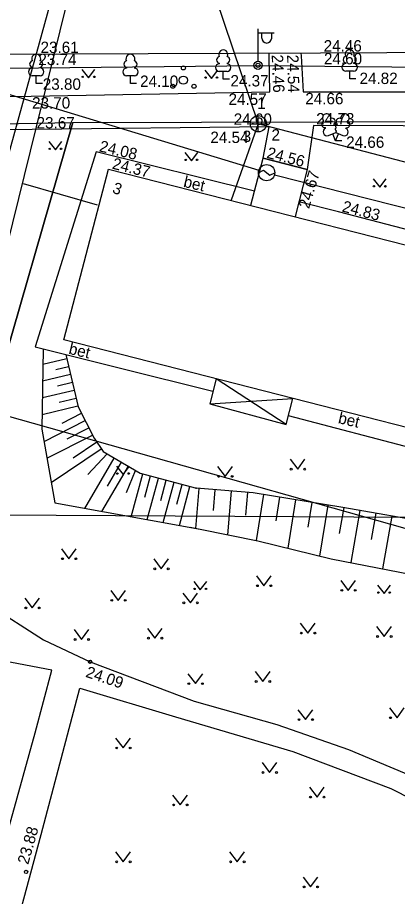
# Model space of a CAD drawing. Extents: x 714391 to 714584, y 6589993 to 6590151.
# Drawn here: x 714529 to 714552.3, y 6590039.4 to 6590093.4 of the extents above; entities that cross this region are included whole.
import ezdxf

# ---------------------------------------------------------------- set-up
doc = ezdxf.new("R2010")
doc.units = 0
for name, color, linetype in [('HALJASTUS', 7, 'Continuous'), ('HOONE', 7, 'Continuous'), ('HOONEDET', 7, 'Continuous'), ('KKAEV', 7, 'Continuous'), ('KORGUS', 7, 'Continuous'), ('KTRASS', 7, 'Continuous'), ('MPKAABEL', 7, 'Continuous'), ('POST', 7, 'Continuous'), ('PUU', 7, 'Continuous'), ('RELJEEF', 7, 'Continuous'), ('SKTRASS', 7, 'Continuous'), ('TEE', 7, 'Continuous'), ('TORU NR', 7, 'Continuous'), ('TTRASS', 7, 'Continuous'), ('Слой 1', 7, 'Continuous')]:
    doc.layers.add(name, color=color, linetype=linetype)

msp = doc.modelspace()

# ---------------------------------------------------------------- linework, layer by layer
at = {"layer": 'HALJASTUS'}
for p, q in [((714532.967, 6590090.202), (714533.372, 6590089.697)), ((714533.372, 6590089.697), (714533.767, 6590090.202)), ((714540.508, 6590090.157), (714540.913, 6590089.652)), ((714540.913, 6590089.652), (714541.308, 6590090.157)), ((714530.935, 6590085.777), (714531.34, 6590085.272)), ((714531.34, 6590085.272), (714531.735, 6590085.777)), ((714539.289, 6590085.1), (714539.694, 6590084.595)), ((714539.694, 6590084.595), (714540.089, 6590085.1)), ((714550.848, 6590083.474), (714551.253, 6590082.969)), ((714551.253, 6590082.969), (714551.648, 6590083.474)), ((714535.09, 6590065.819), (714535.495, 6590065.314)), ((714535.495, 6590065.314), (714535.89, 6590065.819)), ((714541.301, 6590065.801), (714541.764, 6590065.194)), ((714541.764, 6590065.194), (714542.21, 6590065.801)), ((714545.755, 6590066.246), (714546.218, 6590065.639)), ((714546.218, 6590065.639), (714546.664, 6590066.246)), ((714531.707, 6590060.741), (714532.17, 6590060.134)), ((714532.17, 6590060.134), (714532.616, 6590060.741)), ((714537.375, 6590060.121), (714537.838, 6590059.514)), ((714537.838, 6590059.514), (714538.284, 6590060.121)), ((714543.678, 6590059.08), (714544.141, 6590058.473)), ((714544.141, 6590058.473), (714544.587, 6590059.08)), ((714548.862, 6590058.796), (714549.325, 6590058.189)), ((714549.325, 6590058.189), (714549.771, 6590058.796)), ((714539.831, 6590058.73), (714540.236, 6590058.225)), ((714540.236, 6590058.225), (714540.631, 6590058.73)), ((714551.119, 6590058.504), (714551.524, 6590057.999)), ((714551.524, 6590057.999), (714551.919, 6590058.504)), ((714529.455, 6590057.716), (714529.918, 6590057.109)), ((714529.918, 6590057.109), (714530.364, 6590057.716)), ((714534.735, 6590058.181), (714535.198, 6590057.574)), ((714535.198, 6590057.574), (714535.644, 6590058.181)), ((714539.161, 6590058.026), (714539.624, 6590057.419)), ((714539.624, 6590057.419), (714540.07, 6590058.026)), ((714546.376, 6590056.171), (714546.839, 6590055.564)), ((714546.839, 6590055.564), (714547.285, 6590056.171)), ((714532.483, 6590055.776), (714532.946, 6590055.169)), ((714532.946, 6590055.169), (714533.392, 6590055.776)), ((714536.987, 6590055.854), (714537.45, 6590055.247)), ((714537.45, 6590055.247), (714537.896, 6590055.854)), ((714551.063, 6590055.958), (714551.526, 6590055.351)), ((714551.526, 6590055.351), (714551.972, 6590055.958)), ((714539.472, 6590053.061), (714539.935, 6590052.454)), ((714539.935, 6590052.454), (714540.381, 6590053.061)), ((714543.607, 6590053.191), (714544.07, 6590052.584)), ((714544.07, 6590052.584), (714544.516, 6590053.191)), ((714546.234, 6590050.85), (714546.697, 6590050.243)), ((714546.697, 6590050.243), (714547.143, 6590050.85)), ((714551.855, 6590050.966), (714552.318, 6590050.359)), ((714552.318, 6590050.359), (714552.764, 6590050.966)), ((714535.037, 6590049.107), (714535.5, 6590048.5)), ((714535.5, 6590048.5), (714535.946, 6590049.107)), ((714544.025, 6590047.601), (714544.488, 6590046.994)), ((714544.488, 6590046.994), (714544.934, 6590047.601)), ((714546.94, 6590046.089), (714547.403, 6590045.482)), ((714547.403, 6590045.482), (714547.849, 6590046.089)), ((714538.537, 6590045.607), (714539, 6590045)), ((714539, 6590045), (714539.446, 6590045.607)), ((714535.037, 6590042.107), (714535.5, 6590041.5)), ((714535.5, 6590041.5), (714535.946, 6590042.107)), ((714542.037, 6590042.107), (714542.5, 6590041.5)), ((714542.5, 6590041.5), (714542.946, 6590042.107)), ((714546.549, 6590040.566), (714547.012, 6590039.959)), ((714547.012, 6590039.959), (714547.458, 6590040.566))]:
    msp.add_line(p, q, dxfattribs=at)
for centre, radius in [((714539.197, 6590090.299), 0.125), ((714533.019, 6590089.752), 0.0428), ((714533.719, 6590089.752), 0.0452), ((714539.197, 6590089.549), 0.25), ((714540.56, 6590089.707), 0.0428), ((714541.26, 6590089.707), 0.0452), ((714538.547, 6590089.174), 0.125), ((714539.847, 6590089.174), 0.125), ((714530.987, 6590085.327), 0.0428), ((714531.687, 6590085.327), 0.0452), ((714539.341, 6590084.65), 0.0428), ((714540.041, 6590084.65), 0.0452), ((714550.9, 6590083.024), 0.0428), ((714551.6, 6590083.024), 0.0452), ((714535.142, 6590065.37), 0.0428), ((714535.842, 6590065.37), 0.0452), ((714541.363, 6590065.194), 0.055), ((714542.192, 6590065.194), 0.055), ((714545.817, 6590065.639), 0.055), ((714546.646, 6590065.639), 0.055), ((714531.769, 6590060.134), 0.055), ((714532.598, 6590060.134), 0.055), ((714537.437, 6590059.514), 0.055), ((714538.266, 6590059.514), 0.055), ((714539.883, 6590058.28), 0.0428), ((714540.583, 6590058.28), 0.0452), ((714543.74, 6590058.473), 0.055), ((714544.569, 6590058.473), 0.055), ((714548.924, 6590058.189), 0.055), ((714549.753, 6590058.189), 0.055), ((714551.171, 6590058.055), 0.0428), ((714551.871, 6590058.055), 0.0452), ((714529.517, 6590057.109), 0.055), ((714530.346, 6590057.109), 0.055), ((714534.797, 6590057.574), 0.055), ((714535.626, 6590057.574), 0.055), ((714539.223, 6590057.419), 0.055), ((714540.052, 6590057.419), 0.055), ((714546.438, 6590055.564), 0.055), ((714547.267, 6590055.564), 0.055), ((714532.545, 6590055.169), 0.055), ((714533.374, 6590055.169), 0.055), ((714537.049, 6590055.247), 0.055), ((714537.878, 6590055.247), 0.055), ((714551.125, 6590055.351), 0.055), ((714551.954, 6590055.351), 0.055), ((714539.534, 6590052.454), 0.055), ((714540.363, 6590052.454), 0.055), ((714543.669, 6590052.584), 0.055), ((714544.498, 6590052.584), 0.055), ((714546.296, 6590050.243), 0.055), ((714547.125, 6590050.243), 0.055), ((714551.917, 6590050.359), 0.055), ((714535.099, 6590048.5), 0.055), ((714535.928, 6590048.5), 0.055), ((714544.087, 6590046.994), 0.055), ((714544.916, 6590046.994), 0.055), ((714547.002, 6590045.482), 0.055), ((714547.831, 6590045.482), 0.055), ((714538.599, 6590045), 0.055), ((714539.428, 6590045), 0.055), ((714535.099, 6590041.5), 0.055), ((714535.928, 6590041.5), 0.055), ((714542.099, 6590041.5), 0.055), ((714542.928, 6590041.5), 0.055), ((714546.611, 6590039.959), 0.055), ((714547.44, 6590039.959), 0.055)]:
    msp.add_circle(centre, radius, dxfattribs=at)
at = {"layer": 'HOONE'}
for p, q in [((714543.807, 6590083.861), (714544.107, 6590084.011)), ((714544.107, 6590084.011), (714544.507, 6590083.711)), ((714544.507, 6590083.711), (714544.807, 6590083.861)), ((714544.792, 6590083.737), (714563.294, 6590079.021))]:
    msp.add_line(p, q, dxfattribs=at)
for points in [[(714462.976, 6590094.666), (714464.039, 6590094.043), (714487.101, 6590093.963), (714494.525, 6590093.286), (714520.217, 6590091.196), (714543.829, 6590084.007)], [(714543.336, 6590081.86), (714544.103, 6590084.747), (714546.8, 6590084.063), (714546.052, 6590081.166)], [(714571.553, 6590063.416), (714531.849, 6590073.579), (714534.607, 6590084.082)], [(714534.607, 6590084.082), (714574.255, 6590073.951), (714571.553, 6590063.416)], [(714541.207, 6590071.184), (714540.811, 6590069.652), (714545.499, 6590068.383), (714545.912, 6590069.979)]]:
    msp.add_lwpolyline(points, dxfattribs=at)
msp.add_circle((714544.307, 6590083.861), 0.5, dxfattribs=at)
at = {"layer": 'HOONEDET'}
for p, q in [((714546.8, 6590084.063), (714544.103, 6590084.747)), ((714545.499, 6590068.383), (714541.207, 6590071.184)), ((714540.811, 6590069.652), (714545.912, 6590069.979))]:
    msp.add_line(p, q, dxfattribs=at)
at = {"layer": 'KKAEV'}
for p, q in [((714543.798, 6590086.368), (714543.798, 6590087.368)), ((714543.298, 6590086.868), (714544.298, 6590086.868))]:
    msp.add_line(p, q, dxfattribs=at)
msp.add_circle((714543.798, 6590086.868), 0.5, dxfattribs=at)
at = {"layer": 'KORGUS'}
for centre in [(714533.466, 6590053.803), (714529.534, 6590040.884)]:
    msp.add_circle(centre, 0.1, dxfattribs=at)
at = {"layer": 'KTRASS'}
for p, q in [((714540.165, 6590097.573), (714543.798, 6590086.868)), ((714543.798, 6590086.868), (714542.121, 6590082.162)), ((714563.101, 6590081.794), (714543.798, 6590086.868))]:
    msp.add_line(p, q, dxfattribs=at)
at = {"layer": 'MPKAABEL'}
for points in [[(714460.809, 6590089.818), (714516.791, 6590090.163), (714543.78, 6590090.458), (714574.561, 6590090.139)], [(714558.719, 6590063.793), (714557.614, 6590062.993), (714553.32, 6590062.662), (714527.694, 6590062.802), (714519.691, 6590062.433), (714508.979, 6590063.853), (714473.93, 6590041.599)]]:
    msp.add_lwpolyline(points, dxfattribs=at)
at = {"layer": 'POST'}
for p, q in [((714543.78, 6590090.708), (714543.78, 6590092.708)), ((714543.78, 6590092.458), (714544.78, 6590092.458)), ((714544.007, 6590092.137), (714544.007, 6590092.458)), ((714544.619, 6590092.137), (714544.619, 6590092.458)), ((714543.78, 6590090.458), (714543.78, 6590090.458))]:
    msp.add_line(p, q, dxfattribs=at)
for radius in [0.25, 0.127]:
    msp.add_circle((714543.78, 6590090.458), radius, dxfattribs=at)
msp.add_arc((714544.313, 6590092.137), 0.306, 180, 0, dxfattribs=at)
at = {"layer": 'PUU'}
for p, q in [((714529.917, 6590090.328), (714529.917, 6590090.298)), ((714530.397, 6590090.328), (714530.397, 6590090.298)), ((714535.706, 6590090.324), (714535.706, 6590090.294)), ((714536.186, 6590090.324), (714536.186, 6590090.294)), ((714541.402, 6590090.587), (714541.402, 6590090.557)), ((714541.882, 6590090.082), (714541.402, 6590090.082)), ((714541.642, 6590089.607), (714541.642, 6590090.082)), ((714541.882, 6590090.587), (714541.882, 6590090.557)), ((714549.172, 6590090.602), (714549.172, 6590090.572)), ((714549.652, 6590090.097), (714549.172, 6590090.097)), ((714549.412, 6590089.622), (714549.412, 6590090.097)), ((714549.652, 6590090.602), (714549.652, 6590090.572)), ((714530.397, 6590089.823), (714529.917, 6590089.823)), ((714530.157, 6590089.348), (714530.157, 6590089.823)), ((714536.186, 6590089.819), (714535.706, 6590089.819)), ((714535.946, 6590089.344), (714535.946, 6590089.819)), ((714542.022, 6590089.607), (714541.642, 6590089.607)), ((714549.792, 6590089.622), (714549.412, 6590089.622)), ((714530.537, 6590089.348), (714530.157, 6590089.348)), ((714536.326, 6590089.344), (714535.946, 6590089.344)), ((714548.459, 6590086.803), (714548.444, 6590086.838)), ((714548.644, 6590086.798), (714548.659, 6590086.838)), ((714547.929, 6590086.593), (714547.914, 6590086.633)), ((714548.104, 6590086.148), (714548.549, 6590086.323)), ((714548.549, 6590086.323), (714548.989, 6590086.143)), ((714549.169, 6590086.583), (714549.184, 6590086.623)), ((714548.544, 6590085.813), (714548.369, 6590086.253)), ((714548.544, 6590085.813), (714548.724, 6590086.253)), ((714548.924, 6590085.813), (714548.544, 6590085.813))]:
    msp.add_line(p, q, dxfattribs=at)
msp.add_lwpolyline([(714548.549, 6590086.818), (714548.529, 6590086.743), (714548.529, 6590086.723), (714548.539, 6590086.693), (714548.559, 6590086.658), (714548.564, 6590086.638), (714548.549, 6590086.603), (714548.524, 6590086.553), (714548.519, 6590086.528), (714548.524, 6590086.513), (714548.534, 6590086.483), (714548.569, 6590086.423), (714548.574, 6590086.403), (714548.569, 6590086.383), (714548.554, 6590086.348), (714548.549, 6590086.323)], dxfattribs=at)
for centre, radius, start, end in [((714541.642, 6590091.127), 0.277, 332.5799, 207.4201), ((714549.412, 6590091.142), 0.277, 332.5799, 207.4201), ((714529.967, 6590090.536), 0.212, 105.2441, 257.079), ((714530.157, 6590090.868), 0.277, 332.5799, 207.4201), ((714530.347, 6590090.536), 0.212, 282.921, 74.7559), ((714535.756, 6590090.531), 0.212, 105.2441, 257.079), ((714535.946, 6590090.864), 0.277, 332.5799, 207.4201), ((714536.136, 6590090.531), 0.212, 282.921, 74.7559), ((714541.452, 6590090.795), 0.212, 105.2441, 257.079), ((714541.832, 6590090.795), 0.212, 282.921, 74.7559), ((714549.222, 6590090.81), 0.212, 105.2441, 257.079), ((714549.602, 6590090.81), 0.212, 282.921, 74.7559), ((714529.919, 6590090.061), 0.237, 90, 270), ((714530.394, 6590090.061), 0.237, 270, 90), ((714535.708, 6590090.056), 0.237, 90, 270), ((714536.183, 6590090.056), 0.237, 270, 90), ((714541.404, 6590090.32), 0.237, 90, 270), ((714541.879, 6590090.32), 0.237, 270, 90), ((714549.174, 6590090.335), 0.237, 90, 270), ((714549.649, 6590090.335), 0.237, 270, 90), ((714547.987, 6590087.227), 0.256, 111.5027, 232.5173), ((714547.987, 6590087.227), 0.256, 350.4856, 111.5002), ((714549.123, 6590087.218), 0.256, 67.6168, 188.6314), ((714549.123, 6590087.218), 0.256, 306.5997, 67.6143), ((714547.888, 6590086.831), 0.202, 106.2979, 277.8684), ((714548.33, 6590087.005), 0.202, 305.1345, 116.705), ((714548.777, 6590087.001), 0.202, 62.412, 233.9825), ((714549.216, 6590086.821), 0.202, 261.2486, 72.8191), ((714548.018, 6590086.371), 0.237, 111.5014, 291.5004), ((714548.548, 6590086.58), 0.237, 66.7655, 111.5015), ((714549.079, 6590086.363), 0.237, 247.6166, 67.6155)]:
    msp.add_arc(centre, radius, start, end, dxfattribs=at)
at = {"layer": 'RELJEEF'}
for p, q in [((714530.569, 6590072.097), (714532.033, 6590072.442)), ((714531.354, 6590071.768), (714532.148, 6590071.955)), ((714530.552, 6590071.066), (714532.262, 6590071.468)), ((714531.46, 6590070.766), (714532.377, 6590070.982)), ((714530.535, 6590070.035), (714532.491, 6590070.495)), ((714531.566, 6590069.764), (714532.606, 6590070.008)), ((714530.519, 6590069.003), (714532.72, 6590069.521)), ((714531.742, 6590068.461), (714532.936, 6590069.072)), ((714530.637, 6590067.335), (714533.164, 6590068.627)), ((714532.06, 6590067.501), (714533.392, 6590068.182)), ((714530.818, 6590066.305), (714533.619, 6590067.736)), ((714531.08, 6590064.809), (714534.157, 6590066.895)), ((714532.431, 6590066.329), (714533.876, 6590067.309)), ((714533.15, 6590063.228), (714534.955, 6590066.32)), ((714533.324, 6590065.306), (714534.523, 6590066.572)), ((714534.198, 6590063.039), (714535.819, 6590065.816)), ((714534.53, 6590064.601), (714535.387, 6590066.068)), ((714535.695, 6590064.211), (714536.25, 6590065.564)), ((714535.987, 6590062.717), (714536.699, 6590065.353)), ((714536.832, 6590063.925), (714537.182, 6590065.223)), ((714536.975, 6590062.539), (714537.665, 6590065.092)), ((714537.808, 6590063.706), (714538.147, 6590064.962)), ((714537.963, 6590062.361), (714538.63, 6590064.832)), ((714538.785, 6590063.486), (714539.113, 6590064.701)), ((714538.951, 6590062.182), (714539.596, 6590064.571))]:
    msp.add_line(p, q, dxfattribs=at)
for points in [[(714530.584, 6590073.038), (714530.504, 6590068.094), (714531.299, 6590063.562), (714540.223, 6590061.953)], [(714531.976, 6590072.685), (714532.732, 6590069.472), (714533.719, 6590067.541), (714534.279, 6590066.715), (714536.537, 6590065.397), (714539.992, 6590064.464)], [(714539.957, 6590062), (714540.158, 6590064.451)], [(714539.958, 6590064.473), (714539.992, 6590064.464)], [(714565.692, 6590059.595), (714563.686, 6590060.51), (714558.32, 6590061.614), (714554.618, 6590062.293), (714548.983, 6590063.29), (714543.482, 6590064.178), (714539.992, 6590064.464), (714539.958, 6590064.473)], [(714541.049, 6590063.087), (714541.154, 6590064.369)], [(714541.931, 6590061.605), (714542.151, 6590064.288)], [(714543.033, 6590062.805), (714543.148, 6590064.206)], [(714543.682, 6590061.248), (714544.138, 6590064.072)], [(714544.891, 6590062.463), (714545.125, 6590063.913)], [(714545.631, 6590060.776), (714546.112, 6590063.753)], [(714546.853, 6590062.066), (714547.1, 6590063.594)], [(714547.58, 6590060.3), (714548.087, 6590063.434)], [(714548.792, 6590061.679), (714549.074, 6590063.273)], [(714549.492, 6590059.894), (714550.058, 6590063.099)], [(714550.758, 6590061.314), (714551.043, 6590062.925)], [(714551.455, 6590059.513), (714552.028, 6590062.751)], [(714539.606, 6590062.064), (714540.223, 6590061.953)], [(714539.606, 6590062.064), (714540.223, 6590061.953), (714543.767, 6590061.231), (714548.275, 6590060.13), (714553.23, 6590059.168), (714558.369, 6590057.882), (714560.606, 6590056.851), (714561.638, 6590054.857), (714561.432, 6590053.929), (714559.208, 6590049.705), (714554.662, 6590046.175)]]:
    msp.add_lwpolyline(points, dxfattribs=at)
at = {"layer": 'SKTRASS'}
msp.add_lwpolyline([(714531.495, 6590096.001), (714522.972, 6590065.168), (714519.718, 6590053.426), (714509.807, 6590017.772), (714505.951, 6590002.864)], dxfattribs=at)
at = {"layer": 'TEE'}
msp.add_line((714545.64, 6590068.929), (714557.142, 6590065.913), dxfattribs=at)
for points in [[(714573.651, 6590091.235), (714563.941, 6590091.279), (714547.616, 6590091.212), (714515.821, 6590091.083), (714495.803, 6590091.003), (714475.803, 6590090.885), (714460.229, 6590090.83)], [(714515.67, 6590091.082), (714515.674, 6590090.929), (714515.742, 6590088.532), (714529.854, 6590088.565), (714544.514, 6590088.837), (714544.463, 6590091.007), (714544.458, 6590091.199)], [(714546.418, 6590091.207), (714546.428, 6590091.036), (714546.556, 6590088.84)], [(714546.556, 6590088.84), (714546.656, 6590088.84), (714563.739, 6590088.838), (714563.771, 6590091.085), (714563.774, 6590091.278)], [(714544.103, 6590084.747), (714544.474, 6590086.687), (714529.917, 6590086.508), (714515.394, 6590086.496), (714515.277, 6590077.587)], [(714563.164, 6590078.293), (714563.571, 6590080.29), (714563.722, 6590086.695), (714547.192, 6590086.755), (714546.8, 6590084.063)], [(714533.834, 6590085.137), (714530.086, 6590073.165), (714535.337, 6590071.847), (714541.01, 6590070.424)], [(714543.568, 6590082.732), (714533.834, 6590085.137)], [(714563.025, 6590077.723), (714548.722, 6590081.458), (714546.283, 6590082.061)], [(714523.83, 6590060.323), (714524.838, 6590059.346), (714527.207, 6590057.322), (714530.612, 6590055.143), (714533.466, 6590053.803), (714539.862, 6590051.373), (714544.939, 6590049.949), (714549.327, 6590048.405), (714554.662, 6590046.175), (714555.973, 6590045.43), (714557.565, 6590044.068), (714560.558, 6590042.157), (714562.991, 6590040.414), (714566.112, 6590037.695), (714570.003, 6590051.519), (714571.762, 6590062.449)], [(714525.477, 6590005.373), (714525.684, 6590006.074), (714527.69, 6590005.573), (714531.538, 6590012.432), (714532.385, 6590015.369), (714531.445, 6590019.084), (714529.795, 6590023.709), (714527.067, 6590029.841), (714526.32, 6590032.242), (714526.158, 6590034.948), (714527.384, 6590039.748), (714530.089, 6590049.424), (714531.112, 6590053.289), (714520.888, 6590055.232), (714516.962, 6590040.074), (714512.15, 6590039.854), (714507.831, 6590037.94), (714505.233, 6590035.896), (714491.681, 6590027.029), (714484.169, 6590021.661), (714470.258, 6590012.413)], [(714530.594, 6590004.671), (714529.575, 6590005.355), (714533.957, 6590012.977), (714534.157, 6590015.322), (714534.216, 6590016.497), (714533.749, 6590019.201), (714531.843, 6590023.902), (714529.246, 6590029.211), (714527.989, 6590032.696), (714528.19, 6590034.745), (714530.462, 6590043.175), (714532.838, 6590052.177), (714538.719, 6590050.416), (714545.918, 6590048.286), (714551.944, 6590046.002), (714557.184, 6590043.351), (714560.131, 6590041.46), (714562.296, 6590039.644), (714565.486, 6590037.034), (714564.832, 6590036.22), (714560.292, 6590037.889), (714555.09, 6590040.381)]]:
    msp.add_lwpolyline(points, dxfattribs=at)
at = {"layer": 'TTRASS'}
msp.add_line((714529.363, 6590083.201), (714533.906, 6590081.883), dxfattribs=at)
msp.add_lwpolyline([(714510.928, 6590008.703), (714512.829, 6590017.079), (714522.511, 6590055.684), (714522.522, 6590055.681), (714534.537, 6590104.393)], dxfattribs=at)
at = {"layer": 'Слой 1'}
for points in [[(714478.99, 6590085.97), (714532.4, 6590086.95), (714527.28, 6590069.21), (714523.84, 6590056.54), (714478.28, 6590068.22)], [(714579.84, 6590087.07), (714574.08, 6590064.07), (714572.19, 6590056.5), (714562.09, 6590059.36), (714527.28, 6590069.21), (714532.4, 6590086.95)]]:
    msp.add_lwpolyline(points, close=True, dxfattribs=at)

# ---------------------------------------------------------------- texts
at = {"layer": 'HOONE'}
msp.add_text('3', height=0.7, rotation=340.7456, dxfattribs=at).set_placement((714534.785, 6590082.639))
at = {"layer": 'HOONEDET'}
for p in [(714539.158, 6590082.999), (714532.11, 6590072.734), (714548.659, 6590068.475)]:
    msp.add_text('bet', height=0.7, rotation=346.6797, dxfattribs=at).set_placement(p)
at = {"layer": 'KORGUS'}
for s, p in [('23.61', (714530.423, 6590091.215)), ('24.46', (714547.812, 6590091.307)), ('23.74', (714530.291, 6590090.474)), ('24.60', (714547.829, 6590090.519)), ('23.80', (714530.562, 6590088.957)), ('24.10', (714536.537, 6590089.134)), ('24.37', (714542.086, 6590089.16)), ('24.82', (714550.014, 6590089.31)), ('23.70', (714529.903, 6590087.802)), ('24.57', (714541.967, 6590088.028)), ('24.66', (714546.683, 6590088.065)), ('24.60', (714542.288, 6590086.804)), ('24.73', (714547.354, 6590086.827)), ('23.67', (714530.181, 6590086.58)), ('24.54', (714540.854, 6590085.686)), ('24.66', (714549.192, 6590085.388))]:
    msp.add_text(s, height=0.7, dxfattribs=at).set_placement(p)
for s, rotation, p in [('24.46', 272.4161, (714544.617, 6590091.107)), ('24.54', 271.6181, (714545.563, 6590091.105)), ('24.08', 346.7989, (714533.989, 6590085.176)), ('24.56', 345.6997, (714544.269, 6590084.778)), ('24.37', 346.0179, (714534.78, 6590084.115)), ('24.67', 73.2374, (714546.909, 6590081.609)), ('24.83', 345.5432, (714548.9, 6590081.482)), ('24.09', 341.5811, (714533.147, 6590052.881)), ('23.88', 74.0812, (714529.663, 6590041.299))]:
    msp.add_text(s, height=0.7, rotation=rotation, dxfattribs=at).set_placement(p)
at = {"layer": 'TORU NR'}
for s, p in [('1', (714543.734, 6590087.785)), ('3', (714542.84, 6590085.745)), ('2', (714544.605, 6590085.832))]:
    msp.add_text(s, height=0.7, dxfattribs=at).set_placement(p)

doc.saveas('drawing.dxf')
